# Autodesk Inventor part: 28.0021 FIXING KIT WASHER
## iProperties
Created: 2007-04
Part Number: 28.0021 FIXING KIT WASHER
Document SubType Name: Modeling
Designer: Andy Moles
Material: Steel
Mass: 5.13884 g
Surface Area: 6.41676 cm^2
Volume: 0.654629 cm^3
Density: 7.85 g/cm^3
Author: Andy Moles
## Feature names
1. Revolution1
